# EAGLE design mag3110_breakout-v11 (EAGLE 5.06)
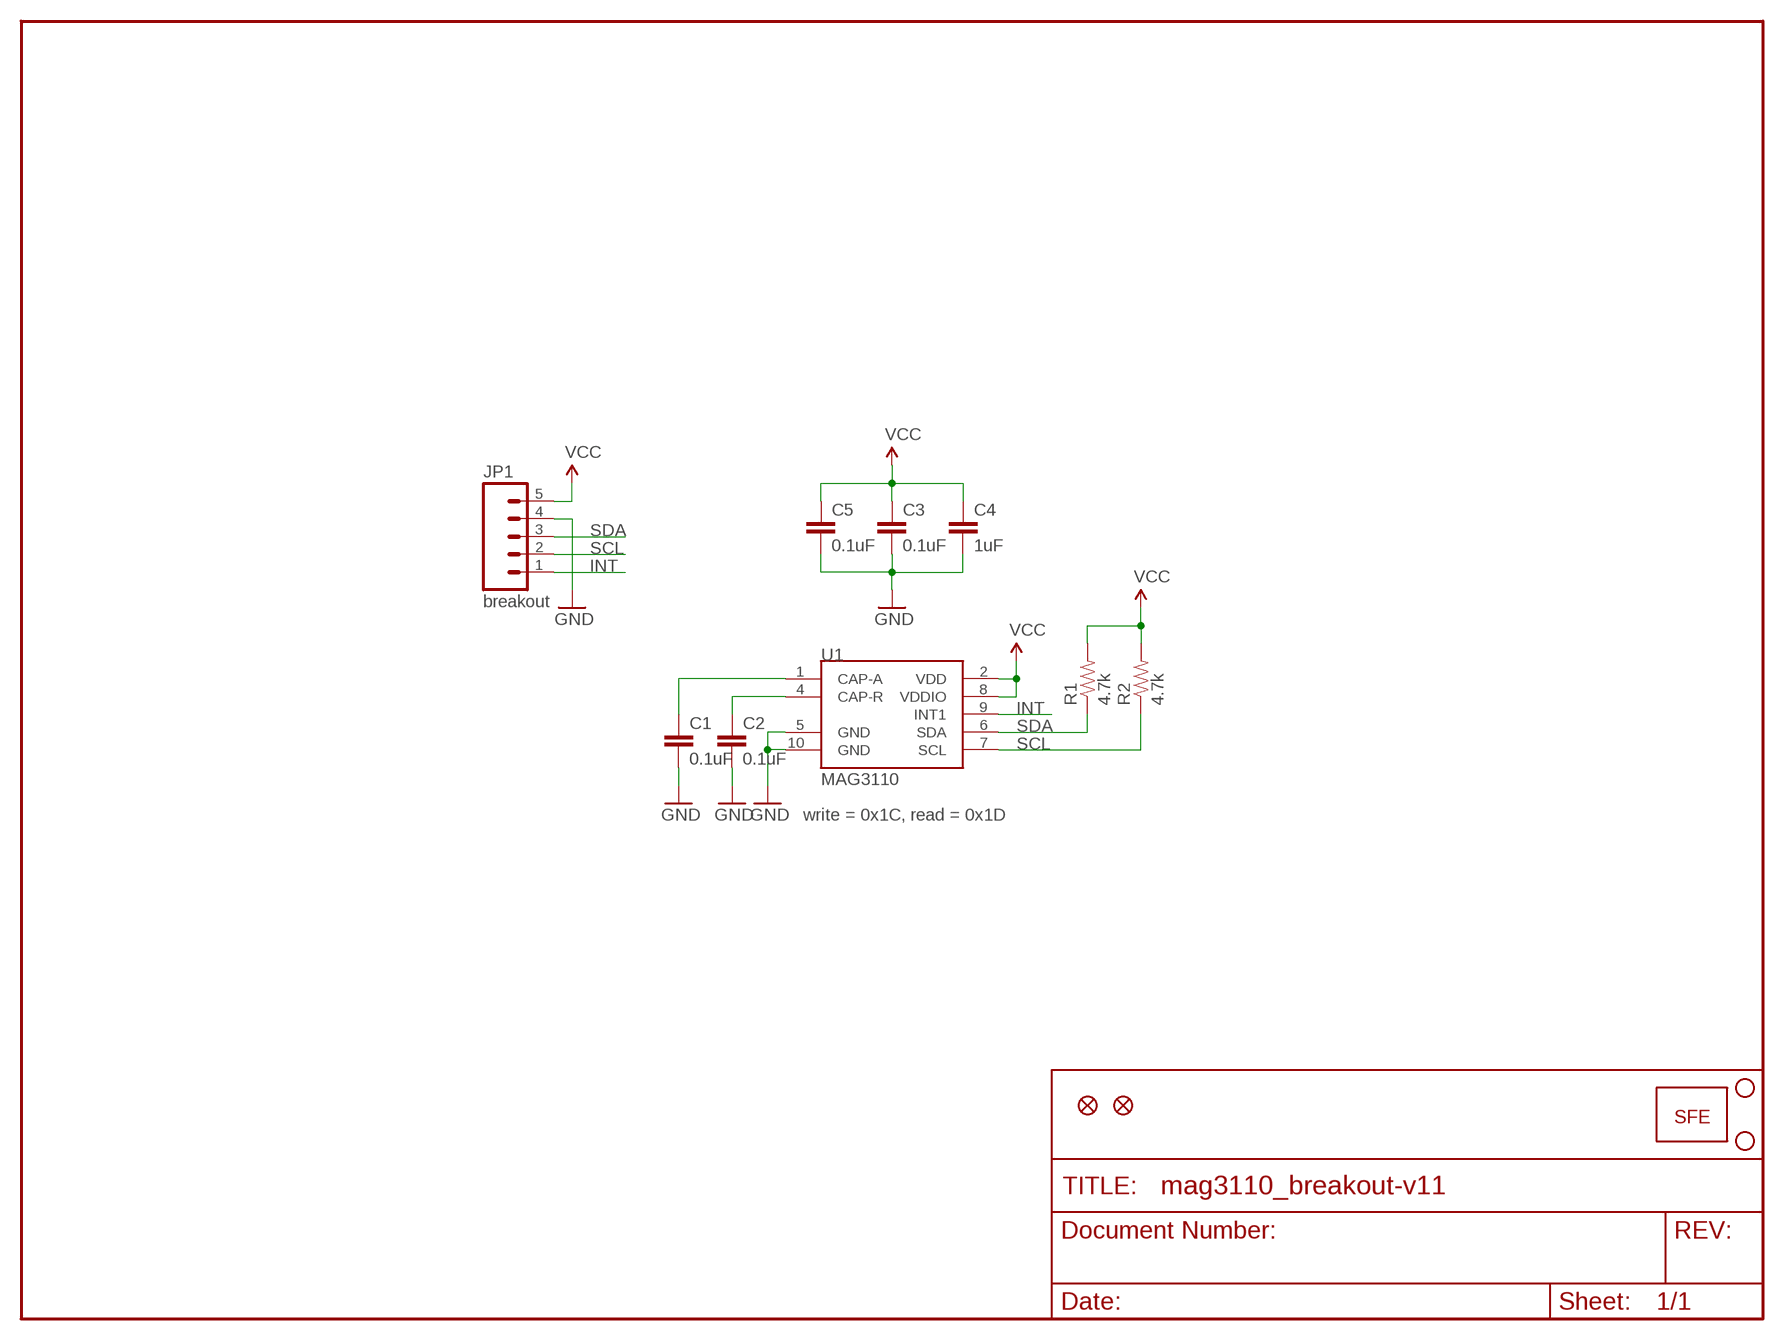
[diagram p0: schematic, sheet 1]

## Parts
C1  0.1uF  CAP0402-CAP  [0402-CAP]
C2  0.1uF  CAP0402-CAP  [0402-CAP]
C3  0.1uF  CAP0402-CAP  [0402-CAP]
C4  1uF  CAP0402-CAP  [0402-CAP]
C5  0.1uF  CAP0402-CAP  [0402-CAP]
JP1  breakout  M05PTH  [1X05]
JP2  STAND-OFF  [STAND-OFF]
JP3  STAND-OFF  [STAND-OFF]
JP4  LOGO-SFESK  [SFE-LOGO-FLAME]
JP5  FIDUCIAL1X2.5  [FIDUCIAL-1X2.5]
JP6  FIDUCIAL1X2.5  [FIDUCIAL-1X2.5]
R1  4.7k  RESISTOR0402-RES  [0402-RES]
R2  4.7k  RESISTOR0402-RES  [0402-RES]
U1  MAG3110  [DFN-10]

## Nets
GND: C1.2 C2.2 C3.2 C4.2 C5.2 JP1.4 U1.5(GND) U1.10(GND)
INT: JP1.1 U1.9(INT1)
N$1: C2.1 U1.4(CAP-R)
N$2: C1.1 U1.1(CAP-A)
SCL: JP1.2 R2.1 U1.7(SCL)
SDA: JP1.3 R1.1 U1.6(SDA)
VCC: C3.1 C4.1 C5.1 JP1.5 R1.2 R2.2 U1.2(VDD) U1.8(VDDIO)

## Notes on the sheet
- write = 0x1C, read = 0x1D

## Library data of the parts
C1-C5 = SparkFun:CAP: Capacitor
JP1 = SparkFun:M05: Header 5 Standard 5-pin 0.1" header. Use with straight break away headers (SKU : PRT-00116), right angle break away headers (PRT-00553), swiss pins (PRT-00743), machine pins (PRT-00117), and female headers (PRT-00115). Molex polarized connector foot print use with SKU : PRT-08230 with associated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
JP2 JP3 = SparkFun:STAND-OFF: Stand Off
JP4 = SparkFun:LOGO-SFE: Spark Fun Electronics PCB Logo
JP5 JP6 = abes:FIDUCIAL: Fiducial Alignment Points
R1 R2 = SparkFun:RESISTOR: Resistor
U1 = SparkFun:MAG3110: 3-axis digital (I2C) magnetometer

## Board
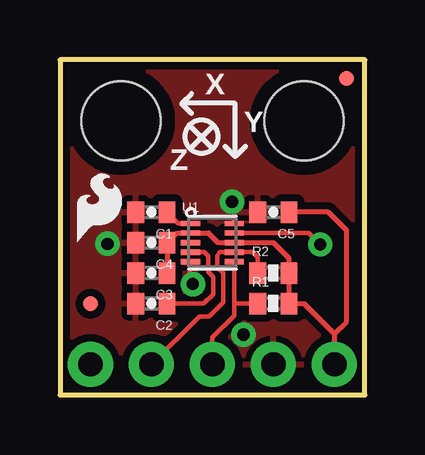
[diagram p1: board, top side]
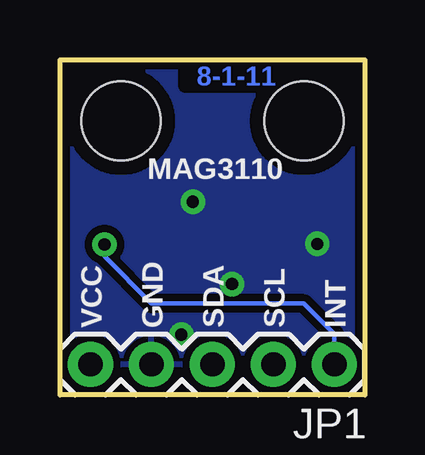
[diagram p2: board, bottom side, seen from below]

Size 12.7 x 13.97 mm. Coordinates in mm from the lower left corner, seen from the top.
Outline: 0,0 12.7,0 12.7,13.97 0,13.97 0,0
Copper layers (1*16): Top 0.035mm / dielectric 1.5mm / Bottom 0.035mm
Design rules "SparkFun": minimum track width 8mil, minimum drill 20mil, track to track 8mil, track to pad 8mil, pad to pad 8mil, via to via 8mil, smd to smd 8mil, copper to edge 8mil, drill to drill 8mil, minimum pad ring 12mil, minimum via ring 10mil, stop-mask expansion 4mil, vias tented up to drill 20mil, thermal gap 10mil

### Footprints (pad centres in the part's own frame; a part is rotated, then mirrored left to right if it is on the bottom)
0402-CAP = smd 0.7 x 0.9: 1 -0.65,0; 2 0.65,0
1X05 = drill 1.016 pad 1.88 round: 1 0,0; 2 2.54,0; 3 5.08,0; 4 7.62,0; 5 10.16,0
STAND-OFF = hole 3.302: 0,0
FIDUCIAL-1X2.5 = smd 0.635 x 0.635: 1 0,0
0402-RES = smd 0.7 x 0.9: 1 -0.65,0; 2 0.65,0
DFN-10 = smd 0.8 x 0.22: 1 -0.91,0.8; 2 -0.91,0.4; 3 -0.91,0; 4 -0.91,-0.4; 5 -0.91,-0.8; 6 0.91,-0.8; 7 0.91,-0.4; 8 0.91,0; 9 0.91,0.4; 10 0.91,0.8

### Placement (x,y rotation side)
C1  3.81,7.62 180 top
C2  3.81,3.81 180 top
C3  3.81,5.08 180 top
C4  3.81,6.35 180 top
C5  8.89,7.62 180 top
JP1  1.27,1.27 180 bottom
JP2  2.54,11.43 0 top
JP3  10.16,11.43 0 top
JP4  0.71,6.4 0 top
JP5  11.94,13.21 0 top
JP6  1.27,3.81 0 top
R1  8.89,3.81 0 top
R2  8.89,5.08 0 top
U1  6.35,6.35 0 top

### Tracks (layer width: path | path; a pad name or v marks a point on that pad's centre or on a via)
GND  (via drill 0.51)
  Top 0.178: U1.5 5.36,4.75 v5.54,4.62 | U1.10 7.26,7.62
  other vias: 7.16,8.05 7.65,2.51 1.98,6.3
  pour Bottom (isolate 0.305): 0,13.97 0,0 12.7,0 12.7,13.97
  pour Top (isolate 0.305): 0,13.97 0,0 12.7,0 12.7,13.97
INT  (via drill 0.51)
  Top 0.178: U1.9 10.37,6.75 v10.85,6.27
  Bottom 0.178: JP1.1 1.27,2.54 2.54,3.81 8.89,3.81 10.85,5.77 v10.85,6.27
N$1
  Top 0.178: C2.1 5.99,3.81 6.38,4.19 6.38,4.93 6.17,5.13 6.17,5.79 6.01,5.95 U1.4
N$2
  Top 0.178: U1.1 4.93,7.15 C1.1
SCL
  Top 0.178: R2.1 8.23,5.74 8.02,5.95 U1.7 6.66,5.95 6.55,5.79 6.55,5.31 6.81,5.08 6.81,3.86 6.22,3.28 5.82,3.28 JP1.2
SDA
  Top 0.178: JP1.3 6.35,2.39 7.26,3.3 7.26,3.81 | 7.26,3.81 U1.6 | 7.26,3.81 R1.1
VCC
  Top 0.178: 6.18,6.75 6.2,6.77
  Top 0.203: C3.1 C4.1 4.86,6.75 U1.2 6.18,6.75 6.58,6.35 U1.8 8.89,6.35 9.54,5.7 R2.2 R1.2 10.16,3.81 11.43,2.54 | 11.43,2.54 JP1.5 | C5.1 11.18,7.62 11.94,6.86 11.94,3.05 11.43,2.54

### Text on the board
Bottom: 8-1-11
tPlace: X | Y | Z
bPlace: MAG3110 | INT | SCL | SDA | GND | VCC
